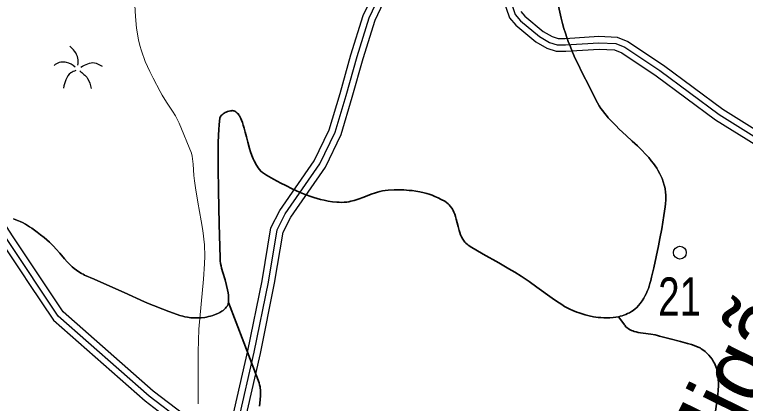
# Model space of a CAD drawing. Extents: x -64005 to -55000, y -89025 to -80000.
# Drawn here: x -60187 to -59043, y -85720 to -85111 of the extents above; entities that cross this region are included whole.
import ezdxf
from ezdxf.enums import TextEntityAlignment as Align

# ---------------------------------------------------------------- set-up
doc = ezdxf.new("R2010")
doc.units = 0
doc.header["$LTSCALE"] = 32
doc.linetypes.add('LONG_DASHED', pattern=[7.5, 6, -1.5])
for name, color, linetype, lineweight in [('2', 7, 'Continuous', 25), ('24', 7, 'Continuous', 25), ('25', 7, 'Continuous', 35), ('33', 7, 'Continuous', 25), ('39', 7, 'LONG_DASHED', 25), ('52', 7, 'Continuous', 25), ('8', 7, 'Continuous', 25)]:
    doc.layers.add(name, color=color, linetype=linetype, lineweight=lineweight)
doc.layers.add('38', color=7, linetype='Continuous')
doc.layers.add('46', color=7, linetype='Continuous')

msp = doc.modelspace()

# ---------------------------------------------------------------- linework, layer by layer
at = {"layer": '2', "lineweight": 13}
msp.add_lwpolyline([(-59899.5, -85720.74), (-59899.22, -85692.22), (-59899.23, -85639.05), (-59898.49, -85603.86), (-59891.01, -85525.24), (-59889.28, -85501.29), (-59888.97, -85489.28), (-59889.52, -85471.33), (-59891.99, -85449.04), (-59894.39, -85434.24), (-59899.9, -85404.71), (-59903.7, -85382.53), (-59905.19, -85371.41), (-59905.98, -85362.76), (-59907.18, -85345.39), (-59908.93, -85332.48), (-59909.8, -85328.06), (-59929.28, -85280.91), (-59934.93, -85269.44), (-59939.34, -85262.13), (-59948.84, -85247.83), (-59955.8, -85236.97), (-59959.01, -85231.37), (-59969.98, -85210.72), (-59975.15, -85200.29), (-59982.22, -85184.33), (-59988.13, -85167.82), (-59990.54, -85159.3), (-59992.62, -85150.25), (-59995.62, -85132.08), (-59997.46, -85113.86), (-59999.55, -85077.31)], dxfattribs=at)
at = {"layer": '24'}
for points in [[(-59349.37, -85033.57), (-59331.13, -85116.5), (-59329.1, -85124.94), (-59326.92, -85132.77), (-59324.66, -85140.05), (-59322.36, -85146.83), (-59320.06, -85153.13), (-59317.79, -85159.01), (-59313.26, -85169.94), (-59309.05, -85179.43), (-59305.21, -85187.67), (-59298.24, -85201.99), (-59287.46, -85223.28), (-59276.78, -85244.45), (-59274.3, -85249.16), (-59271.67, -85253.59), (-59268.95, -85257.78), (-59266.14, -85261.75), (-59263.28, -85265.51), (-59260.39, -85269.08), (-59257.48, -85272.49), (-59251.6, -85278.93), (-59245.84, -85284.83), (-59240.26, -85290.25), (-59229.54, -85300.26), (-59220.08, -85308.95), (-59211.92, -85316.61), (-59204.97, -85323.42), (-59199.13, -85329.49), (-59194.25, -85334.93), (-59190.19, -85339.81), (-59186.83, -85344.17), (-59184.04, -85348.07), (-59181.74, -85351.56), (-59179.83, -85354.67), (-59176.74, -85360.26), (-59174.66, -85364.57), (-59173.24, -85367.88), (-59171.35, -85372.98), (-59169.76, -85378.25), (-59169.05, -85381.16), (-59168.53, -85383.91), (-59167.84, -85389.1), (-59167.55, -85393.69), (-59167.49, -85397.71), (-59167.57, -85401.25), (-59167.98, -85407.44), (-59168.45, -85412.08), (-59169.36, -85418.99), (-59170.39, -85425.83), (-59173.8, -85446.37), (-59176.6, -85461.74), (-59178.85, -85473.26), (-59182.43, -85490.53), (-59186.27, -85507.8), (-59189.6, -85522.3), (-59190.96, -85527.66), (-59192.26, -85532.32), (-59193.52, -85536.36), (-59194.72, -85539.86)], [(-59194.72, -85539.86), (-59193.52, -85536.36), (-59192.26, -85532.32), (-59190.96, -85527.66), (-59189.6, -85522.3), (-59186.27, -85507.8), (-59182.43, -85490.53), (-59178.85, -85473.26), (-59176.6, -85461.74), (-59173.8, -85446.37), (-59170.39, -85425.83), (-59169.36, -85418.99), (-59168.45, -85412.08), (-59167.98, -85407.44), (-59167.57, -85401.25), (-59167.49, -85397.71), (-59167.55, -85393.69), (-59167.84, -85389.1), (-59168.53, -85383.91), (-59169.05, -85381.16), (-59169.76, -85378.25), (-59171.35, -85372.98), (-59173.24, -85367.88), (-59174.66, -85364.57), (-59176.74, -85360.26), (-59179.83, -85354.67), (-59181.74, -85351.56), (-59184.04, -85348.07), (-59186.83, -85344.17), (-59190.19, -85339.81), (-59194.25, -85334.93), (-59199.13, -85329.49), (-59204.97, -85323.42), (-59211.92, -85316.61), (-59220.08, -85308.95), (-59229.54, -85300.26), (-59240.26, -85290.25), (-59245.84, -85284.83), (-59251.6, -85278.93), (-59257.48, -85272.49), (-59260.39, -85269.08), (-59263.28, -85265.51), (-59266.14, -85261.75), (-59268.95, -85257.78), (-59271.67, -85253.59), (-59274.3, -85249.16), (-59276.78, -85244.45), (-59287.46, -85223.28), (-59298.24, -85201.99), (-59305.21, -85187.67), (-59309.05, -85179.43), (-59313.26, -85169.94), (-59317.79, -85159.01), (-59320.06, -85153.13), (-59322.36, -85146.83), (-59324.66, -85140.05), (-59326.92, -85132.77), (-59329.1, -85124.94), (-59331.13, -85116.5), (-59349.37, -85033.57)], [(-59795.67, -85360.49), (-59798.46, -85358.31), (-59800.98, -85355.95), (-59803.24, -85353.45), (-59805.29, -85350.84), (-59807.14, -85348.14), (-59808.82, -85345.39), (-59810.34, -85342.61), (-59811.72, -85339.82), (-59812.99, -85337.03), (-59815.24, -85331.43), (-59817.14, -85325.99), (-59818.77, -85320.77), (-59821.52, -85310.88), (-59823.71, -85302.29), (-59825.56, -85294.99), (-59827.2, -85288.9), (-59828.68, -85283.86), (-59830.06, -85279.73), (-59831.33, -85276.37), (-59832.52, -85273.64), (-59833.62, -85271.43), (-59834.64, -85269.64), (-59835.58, -85268.2), (-59836.43, -85267.03), (-59838.02, -85265.21), (-59839.29, -85264.05), (-59840.3, -85263.29), (-59841.89, -85262.36), (-59843.58, -85261.68), (-59844.64, -85261.46), (-59845.83, -85261.4), (-59847.08, -85261.45), (-59848.36, -85261.6), (-59850.96, -85262.12), (-59853.34, -85262.84), (-59855.45, -85263.65), (-59857.25, -85264.49), (-59858.76, -85265.32), (-59860.01, -85266.12), (-59861.98, -85267.68), (-59863.23, -85268.97), (-59864, -85270), (-59864.86, -85271.64), (-59865.14, -85272.5), (-59865.31, -85273.39), (-59866.36, -85283.12), (-59867.03, -85291.62), (-59867.45, -85299.06), (-59867.89, -85312.09), (-59868.01, -85321.86), (-59867.97, -85336.51), (-59867.81, -85351.17), (-59867.33, -85386.41), (-59866.32, -85439.28), (-59864.95, -85492.14), (-59864.66, -85496.54), (-59864.12, -85500.66), (-59863.42, -85504.5), (-59862.62, -85508.1), (-59860.83, -85514.83)], [(-59490.8, -85449.06), (-59492.5, -85442.72), (-59495.39, -85431.4), (-59496.63, -85427.23), (-59497.86, -85423.66), (-59499.07, -85420.62), (-59500.25, -85418.05), (-59501.4, -85415.88), (-59502.51, -85414.04), (-59504.67, -85410.99), (-59506.51, -85408.86), (-59508.03, -85407.35), (-59510.54, -85405.26), (-59513.35, -85403.39), (-59518.8, -85400.34), (-59523.95, -85397.8), (-59528.79, -85395.68), (-59533.34, -85393.91), (-59537.62, -85392.43), (-59541.65, -85391.2), (-59545.43, -85390.17), (-59552.52, -85388.56), (-59558.74, -85387.46), (-59564.18, -85386.72), (-59568.94, -85386.23), (-59577.25, -85385.67), (-59583.47, -85385.48), (-59592.75, -85385.51), (-59601.97, -85385.83), (-59606.51, -85386.25), (-59610.78, -85386.95), (-59614.78, -85387.86), (-59618.52, -85388.88), (-59622.03, -85389.98), (-59628.62, -85392.28), (-59640.14, -85396.7), (-59648.78, -85399.91), (-59655.26, -85402), (-59660.12, -85403.3), (-59663.76, -85404.07), (-59666.5, -85404.52), (-59670.59, -85404.96), (-59674.69, -85405.08), (-59678.47, -85404.97), (-59682.13, -85404.76), (-59689.2, -85404.05), (-59695.81, -85403.05), (-59701.99, -85401.83), (-59707.77, -85400.45), (-59713.18, -85398.98), (-59718.23, -85397.43), (-59722.96, -85395.86), (-59731.8, -85392.6), (-59739.5, -85389.44), (-59746.22, -85386.48), (-59752.08, -85383.76), (-59762.28, -85378.73), (-59769.9, -85374.79), (-59781.27, -85368.68), (-59792.57, -85362.44), (-59795.67, -85360.49)], [(-60046.69, -85532.27), (-60061.83, -85525.56), (-60076.97, -85518.86), (-60079.4, -85517.72), (-60081.69, -85516.53), (-60085.94, -85513.98), (-60089.73, -85511.33), (-60093.15, -85508.65), (-60096.24, -85505.97), (-60099.05, -85503.35), (-60104.15, -85498.16), (-60108.48, -85493.4), (-60115.95, -85484.8), (-60121.6, -85478.31), (-60125.96, -85473.51), (-60129.33, -85470), (-60131.93, -85467.43), (-60135.97, -85463.71), (-60140.2, -85460.18), (-60146, -85455.66), (-60151.14, -85451.76), (-60155.69, -85448.44), (-60159.7, -85445.63), (-60163.23, -85443.27), (-60169.46, -85439.43), (-60174.16, -85436.82), (-60177.71, -85435.04), (-60180.38, -85433.83), (-60184.4, -85432.21), (-60188.44, -85430.85)], [(-60188.44, -85430.85), (-60184.4, -85432.21), (-60180.38, -85433.83), (-60177.71, -85435.04), (-60174.16, -85436.82), (-60169.46, -85439.43), (-60163.23, -85443.27), (-60159.7, -85445.63), (-60155.69, -85448.44), (-60151.14, -85451.76), (-60146, -85455.66), (-60140.2, -85460.18), (-60135.97, -85463.71), (-60131.93, -85467.43), (-60129.33, -85470), (-60125.96, -85473.51), (-60121.6, -85478.31), (-60115.95, -85484.8), (-60108.48, -85493.4), (-60104.15, -85498.16), (-60099.05, -85503.35), (-60096.24, -85505.97), (-60093.15, -85508.65), (-60089.73, -85511.33), (-60085.94, -85513.98), (-60081.69, -85516.53), (-60079.4, -85517.72), (-60076.97, -85518.86), (-60061.83, -85525.56), (-60046.69, -85532.27)], [(-59241.42, -85584.29), (-59249.79, -85585.49), (-59255, -85585.91), (-59259.96, -85586.05), (-59264.65, -85585.95), (-59269.08, -85585.68), (-59273.24, -85585.27), (-59277.15, -85584.76), (-59280.8, -85584.16), (-59287.61, -85582.77), (-59293.5, -85581.28), (-59298.57, -85579.78), (-59302.93, -85578.33), (-59306.67, -85576.96), (-59313.03, -85574.34), (-59317.62, -85572.23), (-59320.95, -85570.56), (-59325.73, -85567.94), (-59330.24, -85565.19), (-59338.25, -85559.89), (-59345.21, -85555.08), (-59369.39, -85537.66), (-59381.52, -85529.06), (-59387.63, -85524.9), (-59393.78, -85520.87), (-59403.91, -85514.57), (-59412.93, -85509.21), (-59428.94, -85500.03), (-59453.04, -85486.3), (-59464.92, -85479.26), (-59470.78, -85475.65), (-59476.56, -85471.96), (-59478.49, -85470.57), (-59480.2, -85469.09), (-59481.72, -85467.54), (-59483.06, -85465.93), (-59484.25, -85464.28), (-59485.31, -85462.61), (-59487.12, -85459.16), (-59488.59, -85455.72), (-59489.79, -85452.34), (-59490.8, -85449.06)], [(-59860.83, -85514.83), (-59857.27, -85526.55), (-59854.72, -85535.31), (-59853.15, -85541.86), (-59852.26, -85546.78), (-59851.82, -85550.46), (-59851.62, -85553.22), (-59851.59, -85557.37), (-59851.96, -85561.93)], [(-59851.96, -85561.93), (-59852.16, -85562.97), (-59852.54, -85564.3), (-59853.02, -85565.51), (-59854.17, -85567.68), (-59855.44, -85569.47), (-59856.73, -85570.96), (-59857.98, -85572.2), (-59860.38, -85574.22), (-59862.33, -85575.6), (-59865.42, -85577.47), (-59868.62, -85579.08), (-59872.53, -85580.74), (-59876.24, -85582.09), (-59879.74, -85583.17), (-59883.05, -85584.03), (-59886.17, -85584.71), (-59889.1, -85585.22), (-59894.61, -85585.9), (-59899.44, -85586.18), (-59903.66, -85586.19), (-59907.33, -85586.03), (-59910.53, -85585.77), (-59916.08, -85585.02), (-59920.19, -85584.23), (-59923.24, -85583.52), (-59927.74, -85582.25), (-59932.16, -85580.76), (-59944.98, -85576.02), (-59954.6, -85572.4), (-59968.96, -85566.74), (-59976.09, -85563.78), (-59983.15, -85560.69), (-60014.92, -85546.48), (-60046.69, -85532.27)], [(-60046.69, -85532.27), (-60014.92, -85546.48), (-59983.15, -85560.69), (-59976.09, -85563.78), (-59968.96, -85566.74), (-59954.6, -85572.4), (-59944.98, -85576.02), (-59932.16, -85580.76), (-59927.74, -85582.25), (-59923.24, -85583.52), (-59920.19, -85584.23), (-59916.08, -85585.02), (-59910.53, -85585.77), (-59907.33, -85586.03), (-59903.66, -85586.19), (-59899.44, -85586.18), (-59894.61, -85585.9), (-59889.1, -85585.22), (-59886.17, -85584.71), (-59883.05, -85584.03), (-59879.74, -85583.17), (-59876.24, -85582.09), (-59872.53, -85580.74), (-59868.62, -85579.08), (-59865.42, -85577.47), (-59862.33, -85575.6), (-59860.38, -85574.22), (-59857.98, -85572.2), (-59856.73, -85570.96), (-59855.44, -85569.47), (-59854.17, -85567.68), (-59853.02, -85565.51), (-59852.54, -85564.3), (-59852.16, -85562.97), (-59851.96, -85561.93)], [(-59194.72, -85539.86), (-59195.87, -85542.91), (-59198.14, -85548.18), (-59200.07, -85552.08), (-59201.68, -85554.98), (-59204.34, -85559.27), (-59207.36, -85563.5), (-59210, -85566.69), (-59212.74, -85569.53), (-59215.56, -85572.04), (-59218.43, -85574.25), (-59221.34, -85576.2), (-59224.27, -85577.9), (-59227.2, -85579.38), (-59230.13, -85580.67), (-59233.04, -85581.77), (-59235.92, -85582.71), (-59238.77, -85583.5), (-59241.42, -85584.29)], [(-59241.42, -85584.29), (-59238.77, -85583.5), (-59235.92, -85582.71), (-59233.04, -85581.77), (-59230.13, -85580.67), (-59227.2, -85579.38), (-59224.27, -85577.9), (-59221.34, -85576.2), (-59218.43, -85574.25), (-59215.56, -85572.04), (-59212.74, -85569.53), (-59210, -85566.69), (-59207.36, -85563.5), (-59204.34, -85559.27), (-59201.68, -85554.98), (-59200.07, -85552.08), (-59198.14, -85548.18), (-59195.87, -85542.91), (-59194.72, -85539.86)], [(-59851.96, -85561.93), (-59828.02, -85624.83), (-59804.07, -85687.73), (-59803.09, -85690.76), (-59802.4, -85693.86), (-59802.08, -85695.97), (-59801.82, -85698.81), (-59801.69, -85702.64), (-59801.85, -85707.76), (-59802.39, -85714.5), (-59803.51, -85724.38)], [(-59180.6, -85613.52), (-59184.04, -85612.8), (-59190.71, -85611.74), (-59202.63, -85610.19), (-59207.04, -85609.51), (-59210.81, -85608.79), (-59214.01, -85608.03), (-59216.73, -85607.24), (-59219.03, -85606.45), (-59220.97, -85605.65), (-59224.19, -85604.03), (-59226.45, -85602.59), (-59228.04, -85601.36), (-59230.26, -85599.29), (-59231.28, -85598.14), (-59232.24, -85596.9), (-59239.39, -85587.08), (-59241.42, -85584.29)], [(-59089.49, -85732.08), (-59087.36, -85717.72), (-59086.09, -85706.96), (-59085.45, -85698.88), (-59085.2, -85692.83), (-59085.15, -85688.29), (-59085.36, -85681.48), (-59085.92, -85674.67), (-59086.45, -85671.17), (-59087.2, -85667.9), (-59088.11, -85664.85), (-59089.14, -85662.02), (-59090.25, -85659.4), (-59091.42, -85656.98), (-59092.62, -85654.75), (-59095.14, -85650.71), (-59097.6, -85647.33), (-59099.94, -85644.52), (-59102.12, -85642.2), (-59104.13, -85640.27), (-59105.95, -85638.68), (-59109.28, -85636.11), (-59111.89, -85634.38), (-59113.91, -85633.2), (-59117.01, -85631.64), (-59120.21, -85630.34), (-59127.29, -85627.95), (-59133.5, -85626.06), (-59144.4, -85623.07), (-59160.76, -85618.91), (-59168.92, -85616.77), (-59177.06, -85614.46), (-59180.6, -85613.52)]]:
    msp.add_lwpolyline(points, dxfattribs=at)
at = {"layer": '25'}
for points in [[(-59860.83, -85514.83), (-59862.62, -85508.1), (-59863.42, -85504.5), (-59864.12, -85500.66), (-59864.66, -85496.54), (-59864.95, -85492.14), (-59866.32, -85439.28), (-59867.33, -85386.41), (-59867.81, -85351.17), (-59867.97, -85336.51), (-59868.01, -85321.86), (-59867.89, -85312.09), (-59867.45, -85299.06), (-59867.03, -85291.62), (-59866.36, -85283.12), (-59865.31, -85273.39), (-59865.14, -85272.5), (-59864.86, -85271.64), (-59864, -85270), (-59863.23, -85268.97), (-59861.98, -85267.68), (-59860.01, -85266.12), (-59858.76, -85265.32), (-59857.25, -85264.49), (-59855.45, -85263.65), (-59853.34, -85262.84), (-59850.96, -85262.12), (-59848.36, -85261.6), (-59847.08, -85261.45), (-59845.83, -85261.4), (-59844.64, -85261.46), (-59843.58, -85261.68), (-59841.89, -85262.36), (-59840.3, -85263.29), (-59839.29, -85264.05), (-59838.02, -85265.21), (-59836.43, -85267.03), (-59835.58, -85268.2), (-59834.64, -85269.64), (-59833.62, -85271.43), (-59832.52, -85273.64), (-59831.33, -85276.37), (-59830.06, -85279.73), (-59828.68, -85283.86), (-59827.2, -85288.9), (-59825.56, -85294.99), (-59823.71, -85302.29), (-59821.52, -85310.88), (-59818.77, -85320.77), (-59817.14, -85325.99), (-59815.24, -85331.43), (-59812.99, -85337.03), (-59811.72, -85339.82), (-59810.34, -85342.61), (-59808.82, -85345.39), (-59807.14, -85348.14), (-59805.29, -85350.84), (-59803.24, -85353.45), (-59800.98, -85355.95), (-59798.46, -85358.31), (-59795.67, -85360.49)], [(-59795.67, -85360.49), (-59792.57, -85362.44), (-59781.27, -85368.68), (-59769.9, -85374.79), (-59762.28, -85378.73), (-59752.08, -85383.76), (-59746.22, -85386.48), (-59739.5, -85389.44), (-59731.8, -85392.6), (-59722.96, -85395.86), (-59718.23, -85397.43), (-59713.18, -85398.98), (-59707.77, -85400.45), (-59701.99, -85401.83), (-59695.81, -85403.05), (-59689.2, -85404.05), (-59682.13, -85404.76), (-59678.47, -85404.97), (-59674.69, -85405.08), (-59670.59, -85404.96), (-59666.5, -85404.52), (-59663.76, -85404.07), (-59660.12, -85403.3), (-59655.26, -85402), (-59648.78, -85399.91), (-59640.14, -85396.7), (-59628.62, -85392.28), (-59622.03, -85389.98), (-59618.52, -85388.88), (-59614.78, -85387.86), (-59610.78, -85386.95), (-59606.51, -85386.25), (-59601.97, -85385.83), (-59592.75, -85385.51), (-59583.47, -85385.48), (-59577.25, -85385.67), (-59568.94, -85386.23), (-59564.18, -85386.72), (-59558.74, -85387.46), (-59552.52, -85388.56), (-59545.43, -85390.17), (-59541.65, -85391.2), (-59537.62, -85392.43), (-59533.34, -85393.91), (-59528.79, -85395.68), (-59523.95, -85397.8), (-59518.8, -85400.34), (-59513.35, -85403.39), (-59510.54, -85405.26), (-59508.03, -85407.35), (-59506.51, -85408.86), (-59504.67, -85410.99), (-59502.51, -85414.04), (-59501.4, -85415.88), (-59500.25, -85418.05), (-59499.07, -85420.62), (-59497.86, -85423.66), (-59496.63, -85427.23), (-59495.39, -85431.4), (-59492.5, -85442.72), (-59490.8, -85449.06)], [(-59490.8, -85449.06), (-59489.79, -85452.34), (-59488.59, -85455.72), (-59487.12, -85459.16), (-59485.31, -85462.61), (-59484.25, -85464.28), (-59483.06, -85465.93), (-59481.72, -85467.54), (-59480.2, -85469.09), (-59478.49, -85470.57), (-59476.56, -85471.96), (-59470.78, -85475.65), (-59464.92, -85479.26), (-59453.04, -85486.3), (-59428.94, -85500.03), (-59412.93, -85509.21), (-59403.91, -85514.57), (-59393.78, -85520.87), (-59387.63, -85524.9), (-59381.52, -85529.06), (-59369.39, -85537.66), (-59345.21, -85555.08), (-59338.25, -85559.89), (-59330.24, -85565.19), (-59325.73, -85567.94), (-59320.95, -85570.56), (-59317.62, -85572.23), (-59313.03, -85574.34), (-59306.67, -85576.96), (-59302.93, -85578.33), (-59298.57, -85579.78), (-59293.5, -85581.28), (-59287.61, -85582.77), (-59280.8, -85584.16), (-59277.15, -85584.76), (-59273.24, -85585.27), (-59269.08, -85585.68), (-59264.65, -85585.95), (-59259.96, -85586.05), (-59255, -85585.91), (-59249.79, -85585.49), (-59241.42, -85584.29)], [(-59851.96, -85561.93), (-59851.59, -85557.37), (-59851.62, -85553.22), (-59851.82, -85550.46), (-59852.26, -85546.78), (-59853.15, -85541.86), (-59854.72, -85535.31), (-59857.27, -85526.55), (-59860.83, -85514.83)], [(-59803.51, -85724.38), (-59802.39, -85714.5), (-59801.85, -85707.76), (-59801.69, -85702.64), (-59801.82, -85698.81), (-59802.08, -85695.97), (-59802.4, -85693.86), (-59803.09, -85690.76), (-59804.07, -85687.73), (-59828.02, -85624.83), (-59851.96, -85561.93)], [(-59241.42, -85584.29), (-59239.39, -85587.08), (-59232.24, -85596.9), (-59231.28, -85598.14), (-59230.26, -85599.29), (-59228.04, -85601.36), (-59226.45, -85602.59), (-59224.19, -85604.03), (-59220.97, -85605.65), (-59219.03, -85606.45), (-59216.73, -85607.24), (-59214.01, -85608.03), (-59210.81, -85608.79), (-59207.04, -85609.51), (-59202.63, -85610.19), (-59190.71, -85611.74), (-59184.04, -85612.8), (-59180.6, -85613.52)], [(-59180.6, -85613.52), (-59177.06, -85614.46), (-59168.92, -85616.77), (-59160.76, -85618.91), (-59144.4, -85623.07), (-59133.5, -85626.06), (-59127.29, -85627.95), (-59120.21, -85630.34), (-59117.01, -85631.64), (-59113.91, -85633.2), (-59111.89, -85634.38), (-59109.28, -85636.11), (-59105.95, -85638.68), (-59104.13, -85640.27), (-59102.12, -85642.2), (-59099.94, -85644.52), (-59097.6, -85647.33), (-59095.14, -85650.71), (-59092.62, -85654.75), (-59091.42, -85656.98), (-59090.25, -85659.4), (-59089.14, -85662.02), (-59088.11, -85664.85), (-59087.2, -85667.9), (-59086.45, -85671.17), (-59085.92, -85674.67), (-59085.36, -85681.48), (-59085.15, -85688.29), (-59085.2, -85692.83), (-59085.45, -85698.88), (-59086.09, -85706.96), (-59087.36, -85717.72), (-59089.49, -85732.08)]]:
    msp.add_lwpolyline(points, dxfattribs=at)
at = {"layer": '33'}
for points in [[(-60087.47, -85190.1), (-60087.47, -85179.26), (-60092.81, -85168.12), (-60100.05, -85160.42)], [(-60092, -85193.19), (-60105.2, -85185.77), (-60122.98, -85189.17), (-60124.68, -85190.49)], [(-60082.73, -85193.16), (-60061.75, -85186.34), (-60049.65, -85191.6)], [(-60090.72, -85198.62), (-60098.44, -85202.34), (-60106.46, -85212.9), (-60110.1, -85226.02)], [(-60084.52, -85199.16), (-60072.58, -85210.78), (-60066.6, -85226.7)]]:
    msp.add_spline(points, degree=3, dxfattribs=at)
at = {"layer": '39'}
for points in [[(-59856.44, -85799.36), (-59839.02, -85759.47), (-59811.78, -85639.73), (-59789.47, -85529.87), (-59775.75, -85448.33), (-59762.92, -85422.93), (-59708.86, -85344.82), (-59684.84, -85295.04), (-59667.69, -85237.52), (-59650.53, -85176.58), (-59631.69, -85115.96), (-59605.1, -85059.3), (-59580.22, -85011.23), (-59544.19, -84963.17), (-59509.09, -84917.03)], [(-59509.09, -84917.03), (-59483.96, -84924.96), (-59461.15, -84927.34), (-59443.38, -84926.01), (-59431.44, -84926.28), (-59419.77, -84931.85), (-59416.32, -84937.95), (-59413.14, -84955.46), (-59415.53, -85001.61), (-59419.24, -85052.28), (-59412.08, -85084.11), (-59403.32, -85110.91), (-59395.1, -85120.45), (-59364.86, -85145.39), (-59349.48, -85154.4), (-59337.28, -85158.38), (-59324.28, -85158.11), (-59272.01, -85154.93), (-59245.75, -85156.23), (-59231.7, -85162.07), (-59176.79, -85198.41), (-59083.95, -85267.37), (-59021.08, -85306.62)], [(-59856.44, -85799.36), (-59975.82, -85708.45), (-60118.28, -85583.17), (-60197.23, -85464.77), (-60293.04, -85315.95)]]:
    msp.add_lwpolyline(points, dxfattribs=at)
at = {"layer": '52'}
msp.add_circle((-59145.4, -85483.82), 10, dxfattribs=at)
at = {"layer": '8', "linetype": 'LONG_DASHED'}
for points in [[(-59860.51, -85783.69), (-59848.56, -85756.34), (-59821.56, -85637.63), (-59799.3, -85528.04), (-59785.36, -85445.17), (-59771.53, -85417.81), (-59717.53, -85339.77), (-59694.19, -85291.42), (-59677.29, -85234.74), (-59660.12, -85173.74), (-59641.04, -85112.33), (-59614.07, -85054.88), (-59588.72, -85005.9), (-59552.17, -84957.15), (-59518.01, -84912.11), (-59478.24, -84789.56), (-59408.35, -84571.18)], [(-59426.14, -84939.89), (-59423.19, -84956.1), (-59425.51, -85000.99), (-59429.32, -85053.03), (-59421.73, -85086.77), (-59412.19, -85115.93)], [(-59412.19, -85115.93), (-59402.12, -85127.62), (-59370.61, -85153.61), (-59353.61, -85163.58), (-59338.77, -85168.41), (-59323.87, -85168.1), (-59271.96, -85164.95), (-59247.99, -85166.13), (-59236.42, -85170.94), (-59182.54, -85206.6), (-59089.59, -85275.64), (-59026.59, -85314.98), (-58980.92, -85346.72), (-58905.21, -85407.46), (-58859.2, -85453.19), (-58829.02, -85494.62), (-58814.5, -85528.51), (-58802.27, -85542.17)], [(-60300.84, -85322.31), (-60205.6, -85470.25), (-60175.49, -85515.4), (-60164.38, -85532.07), (-60125.87, -85589.81), (-59982.16, -85716.19), (-59868.75, -85802.56)]]:
    msp.add_lwpolyline(points, dxfattribs=at)
at = {"layer": '8'}
for points in [[(-59844.21, -85796.35), (-59829.48, -85762.61), (-59802, -85641.83), (-59779.64, -85531.7), (-59766.14, -85451.49), (-59754.31, -85428.05), (-59700.19, -85349.87), (-59675.49, -85298.65), (-59658.09, -85240.3), (-59640.94, -85179.42), (-59622.34, -85119.59), (-59596.13, -85063.72), (-59571.72, -85016.56), (-59536.21, -84969.19), (-59505.46, -84928.66)], [(-59394.44, -85105.89), (-59388.08, -85113.28), (-59359.11, -85137.16), (-59345.35, -85145.23), (-59335.79, -85148.35), (-59324.69, -85148.12), (-59272.06, -85144.9), (-59243.51, -85146.33), (-59226.98, -85153.2), (-59171.04, -85190.21), (-59078.3, -85259.1), (-59015.57, -85298.27), (-58968.94, -85330.7), (-58891.87, -85392.51), (-58843.96, -85440.13), (-58811.52, -85484.66), (-58797.4, -85517.61), (-58791.59, -85524.11)], [(-59860.51, -85783.69), (-59969.48, -85700.71), (-60110.69, -85576.53), (-60188.86, -85459.29), (-60285.23, -85309.58)]]:
    msp.add_lwpolyline(points, dxfattribs=at)

# ---------------------------------------------------------------- texts
at = {"layer": '38', "width": 0.75}
msp.add_text('21', height=60, rotation=0.007, dxfattribs=at).set_placement((-59145.84, -85582.64), align=Align.CENTER)
at = {"layer": '46'}
msp.add_text('Vale Migães', height=105, rotation=63.8, dxfattribs=at).set_placement((-59063.58, -85799.24), align=Align.CENTER)

doc.saveas('drawing.dxf')
